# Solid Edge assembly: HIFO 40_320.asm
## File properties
Title: Zylinder
Author: ahadarics
Template: iso assembly.asm
Last saved by: ahadarics
Revision: 46
Application: Solid Edge
Username: ahadarics
Dokumentum tartalom típus: 1
Document Number: HIFO 40/320
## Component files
Profilrohr 40_320.par
Mutter.par
Kolbenstange 40_320.par
Kit_1.par
Kit_2.par
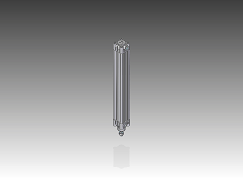
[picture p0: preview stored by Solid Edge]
